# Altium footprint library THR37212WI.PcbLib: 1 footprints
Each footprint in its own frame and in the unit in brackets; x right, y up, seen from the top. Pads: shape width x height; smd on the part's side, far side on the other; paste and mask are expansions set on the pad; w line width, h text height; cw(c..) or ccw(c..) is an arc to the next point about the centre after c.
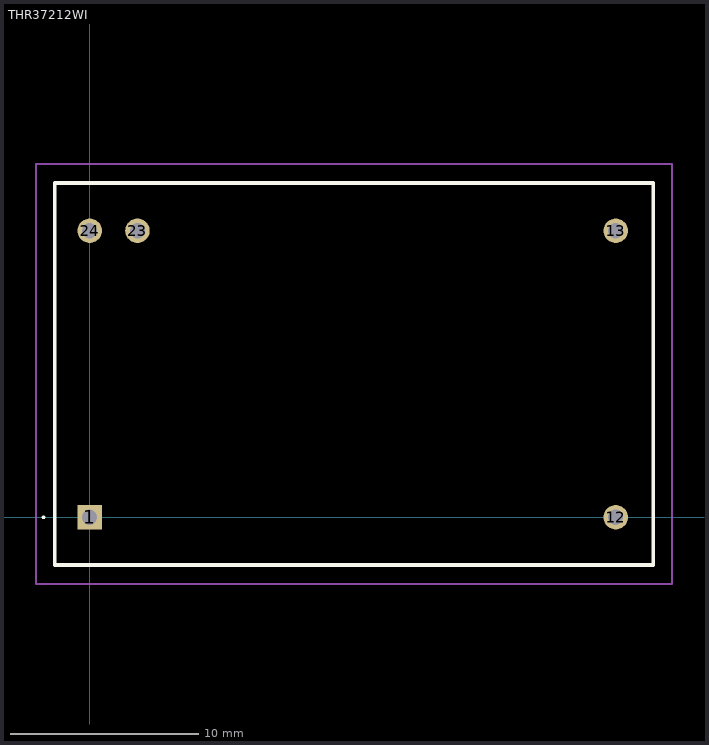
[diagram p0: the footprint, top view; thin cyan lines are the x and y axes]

## THR37212WI [mm]
pads (5):
  rect 1.3x1.3 hole 0.8: 1(0,0)
  round 1.3 hole 0.8: 12(27.94,0) 13(27.94,15.22) 23(2.54,15.22) 24(0,15.22)
Top Overlay:
  lines w0.1: -2.5,0 -2.5,0 ; -2.5,0 ccw(c-2.45,0) -2.4,0 ; -2.5,0 cw(c-2.45,0) -2.4,0 ; -2.4,0 -2.4,0
  lines w0.2: -1.86,-2.54 29.94,-2.54 29.94,17.76 -1.86,17.76 -1.86,-2.54
Mechanical 15:
  lines w0.1: -1.86,-2.54 29.94,-2.54 29.94,17.76 -1.86,17.76 -1.86,-2.54
Mechanical 20:
  lines w0.1: -2.86,-3.54 30.94,-3.54 30.94,18.76 -2.86,18.76 -2.86,-3.54
3D body "THR_3-7212WI.stp": height 5.8, standoff -4.65, extent -10,-3.376 10,3.376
